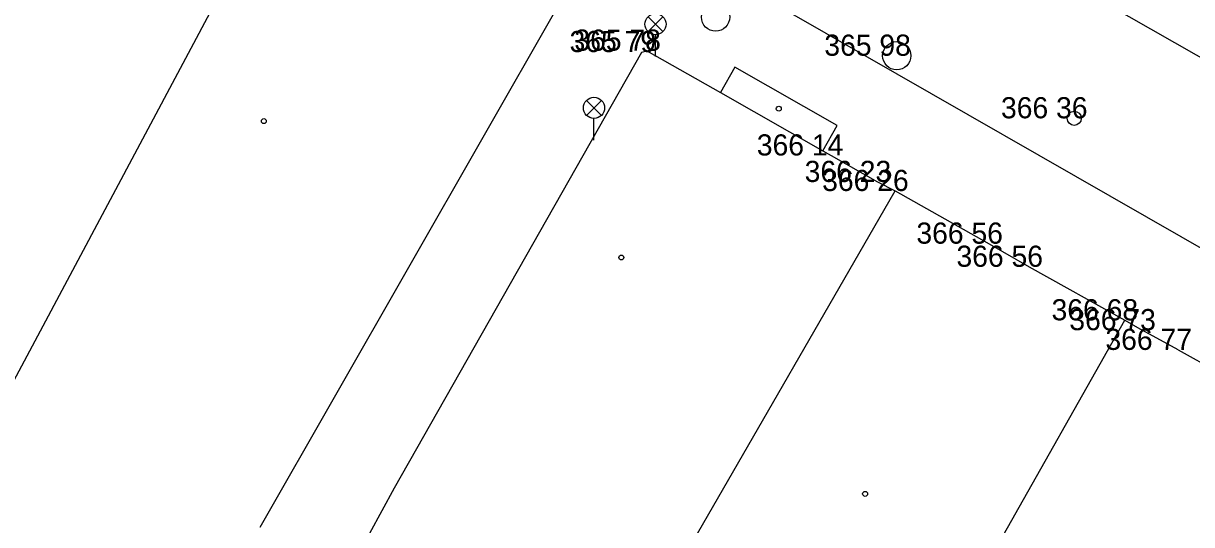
# Model space of a CAD drawing. Extents: x -688316 to -688024, y -973785 to -973591.
# Drawn here: x -688191.59 to -688150.19, y -973692.34 to -973674.55 of the extents above; entities that cross this region are included whole.
import ezdxf

# ---------------------------------------------------------------- set-up
doc = ezdxf.new("R2010")
doc.units = 0
for name, color, linetype in [('Vrstva 10', 7, 'Continuous'), ('Vrstva 27', 7, 'Continuous'), ('Vrstva 28_Verejne osvetleni', 7, 'Continuous'), ('Vrstva 3', 7, 'Continuous'), ('Vrstva 33', 7, 'Continuous'), ('Vrstva 5', 7, 'Continuous'), ('Vrstva 58', 7, 'Continuous'), ('Vrstva 6', 7, 'Continuous')]:
    doc.layers.add(name, color=color, linetype=linetype)

# ---------------------------------------------------------------- blocks, each defined once
blk = doc.blocks.new('B_NESP')
at = {"layer": 'Vrstva 58'}
blk.add_circle((0, 0), 0.875, dxfattribs=at)
blk = doc.blocks.new('LAO')
at = {"layer": 'Vrstva 33'}
for p, q in [((-2.65, 14.16), (2.65, 8.85)), ((-2.65, 8.85), (2.65, 14.16)), ((0, 0), (0, 7.75))]:
    blk.add_line(p, q, dxfattribs=at)
blk.add_circle((0, 11.5), 3.75, dxfattribs=at)
blk = doc.blocks.new('SV')
at = {"layer": 'Vrstva 28_Verejne osvetleni'}
blk.add_circle((0, 0), 2.5, dxfattribs=at)
blk = doc.blocks.new('SAK')
at = {"layer": 'Vrstva 27'}
blk.add_circle((0, 0), 5, dxfattribs=at)

msp = doc.modelspace()

# ---------------------------------------------------------------- linework, layer by layer
at = {"layer": 'Vrstva 10'}
for p, q in [((-688153.18, -973673.87), (-688140.93, -973680.86)), ((-688146.68, -973684.36), (-688164.44, -973674.16))]:
    msp.add_line(p, q, dxfattribs=at)
at = {"layer": 'Vrstva 5'}
for p, q in [((-688194.65, -973692.33), (-688181.87, -973668.34)), ((-688174.12, -973703.78), (-688160.7, -973680.5)), ((-688155.94, -973683.19), (-688152.56, -973685.09)), ((-688165.69, -973708.36), (-688152.56, -973685.09)), ((-688152.56, -973685.09), (-688151.94, -973685.44)), ((-688150.66, -973686.14), (-688143.74, -973689.99))]:
    msp.add_line(p, q, dxfattribs=at)
for points in [[(-688175.06, -973672.3), (-688172.73, -973673.64), (-688172.67, -973673.99), (-688183.21, -973692.44)], [(-688178.44, -973691.03), (-688169.67, -973675.57), (-688169.5, -973675.52), (-688166.89, -973677), (-688163.26, -973679.07), (-688162.96, -973679.24)], [(-688163.26, -973679.07), (-688162.75, -973678.17), (-688166.38, -973676.1), (-688166.89, -973677)], [(-688161.32, -973680.18), (-688160.7, -973680.5), (-688157.36, -973682.37)], [(-688174.94, -973695.02), (-688179.32, -973692.64), (-688178.44, -973691.03)]]:
    msp.add_lwpolyline(points, dxfattribs=at)
at = {"layer": 'Vrstva 6'}
for p, q in [((-688162.96, -973679.24), (-688161.32, -973680.18)), ((-688157.36, -973682.37), (-688155.94, -973683.19)), ((-688150.66, -973686.14), (-688151.94, -973685.44))]:
    msp.add_line(p, q, dxfattribs=at)

# ---------------------------------------------------------------- block references
at = {"layer": 'Vrstva 27', "xscale": 0.1, "yscale": 0.10000000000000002}
for p in [(-688167.06, -973674.33), (-688160.64, -973675.7)]:
    msp.add_blockref('SAK', p, dxfattribs=at)
at = {"layer": 'Vrstva 28_Verejne osvetleni', "xscale": 0.1, "yscale": 0.10000000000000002}
msp.add_blockref('SV', (-688154.35, -973677.92), dxfattribs=at)
at = {"layer": 'Vrstva 33', "xscale": 0.1, "yscale": 0.10000000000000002}
for p in [(-688169.19, -973675.73), (-688171.37, -973678.7)]:
    msp.add_blockref('LAO', p, dxfattribs=at)
at = {"layer": 'Vrstva 58', "xscale": 0.1, "yscale": 0.10000000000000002}
for p in [(-688164.82, -973677.58), (-688164.82, -973677.58), (-688164.82, -973677.58), (-688164.82, -973677.58), (-688183.07, -973678.02), (-688183.07, -973678.02), (-688183.07, -973678.02), (-688183.07, -973678.02), (-688170.4, -973682.86), (-688170.4, -973682.86), (-688170.4, -973682.86), (-688170.4, -973682.86), (-688161.76, -973691.25), (-688161.76, -973691.25), (-688161.76, -973691.25), (-688161.76, -973691.25)]:
    msp.add_blockref('B_NESP', p, dxfattribs=at)

# ---------------------------------------------------------------- texts
at = {"layer": 'Vrstva 3'}
for s, p in [('365 79 ', (-688172.236, -973675.57)), ('365 79 ', (-688172.236, -973675.57)), ('365 79 ', (-688172.236, -973675.57)), ('365 79 ', (-688172.236, -973675.57)), ('365 79 ', (-688172.236, -973675.57)), ('365 79 ', (-688172.236, -973675.57)), ('365 79 ', (-688172.236, -973675.57)), ('365 78 ', (-688172.066, -973675.52)), ('365 78 ', (-688172.066, -973675.52)), ('365 78 ', (-688172.066, -973675.52)), ('365 78 ', (-688172.066, -973675.52)), ('365 78 ', (-688172.066, -973675.52)), ('365 78 ', (-688172.066, -973675.52)), ('365 78 ', (-688172.066, -973675.52)), ('365 98 ', (-688163.206, -973675.7)), ('365 98 ', (-688163.206, -973675.7)), ('365 98 ', (-688163.206, -973675.7)), ('365 98 ', (-688163.206, -973675.7)), ('365 98 ', (-688163.206, -973675.7)), ('365 98 ', (-688163.206, -973675.7)), ('365 98 ', (-688163.206, -973675.7)), ('366 36 ', (-688156.945, -973677.92)), ('366 36 ', (-688156.945, -973677.92)), ('366 36 ', (-688156.945, -973677.92)), ('366 36 ', (-688156.945, -973677.92)), ('366 36 ', (-688156.945, -973677.92)), ('366 36 ', (-688156.945, -973677.92)), ('366 36 ', (-688156.945, -973677.92)), ('366 14 ', (-688165.599, -973679.24)), ('366 14 ', (-688165.599, -973679.24)), ('366 14 ', (-688165.599, -973679.24)), ('366 14 ', (-688165.599, -973679.24)), ('366 14 ', (-688165.599, -973679.24)), ('366 14 ', (-688165.599, -973679.24)), ('366 14 ', (-688165.599, -973679.24)), ('366 23 ', (-688163.903, -973680.18)), ('366 23 ', (-688163.903, -973680.18)), ('366 23 ', (-688163.903, -973680.18)), ('366 23 ', (-688163.903, -973680.18)), ('366 23 ', (-688163.903, -973680.18)), ('366 23 ', (-688163.903, -973680.18)), ('366 23 ', (-688163.903, -973680.18)), ('366 26 ', (-688163.283, -973680.5)), ('366 26 ', (-688163.283, -973680.5)), ('366 26 ', (-688163.283, -973680.5)), ('366 26 ', (-688163.283, -973680.5)), ('366 26 ', (-688163.283, -973680.5)), ('366 26 ', (-688163.283, -973680.5)), ('366 26 ', (-688163.283, -973680.5)), ('366 56 ', (-688159.943, -973682.37)), ('366 56 ', (-688159.943, -973682.37)), ('366 56 ', (-688159.943, -973682.37)), ('366 56 ', (-688159.943, -973682.37)), ('366 56 ', (-688159.943, -973682.37)), ('366 56 ', (-688159.943, -973682.37)), ('366 56 ', (-688159.943, -973682.37)), ('366 56 ', (-688158.523, -973683.19)), ('366 56 ', (-688158.523, -973683.19)), ('366 56 ', (-688158.523, -973683.19)), ('366 56 ', (-688158.523, -973683.19)), ('366 56 ', (-688158.523, -973683.19)), ('366 56 ', (-688158.523, -973683.19)), ('366 56 ', (-688158.523, -973683.19)), ('366 68 ', (-688155.152, -973685.09)), ('366 68 ', (-688155.152, -973685.09)), ('366 68 ', (-688155.152, -973685.09)), ('366 68 ', (-688155.152, -973685.09)), ('366 68 ', (-688155.152, -973685.09)), ('366 68 ', (-688155.152, -973685.09)), ('366 68 ', (-688155.152, -973685.09)), ('366 73 ', (-688154.523, -973685.44)), ('366 73 ', (-688154.523, -973685.44)), ('366 73 ', (-688154.523, -973685.44)), ('366 73 ', (-688154.523, -973685.44)), ('366 73 ', (-688154.523, -973685.44)), ('366 73 ', (-688154.523, -973685.44)), ('366 73 ', (-688154.523, -973685.44)), ('366 77 ', (-688153.243, -973686.14)), ('366 77 ', (-688153.243, -973686.14)), ('366 77 ', (-688153.243, -973686.14)), ('366 77 ', (-688153.243, -973686.14)), ('366 77 ', (-688153.243, -973686.14)), ('366 77 ', (-688153.243, -973686.14)), ('366 77 ', (-688153.243, -973686.14))]:
    msp.add_text(s, height=0.75, dxfattribs=at).set_placement(p)

doc.saveas('drawing.dxf')
